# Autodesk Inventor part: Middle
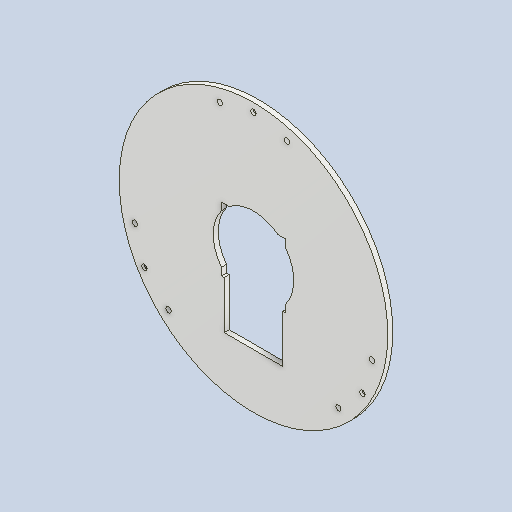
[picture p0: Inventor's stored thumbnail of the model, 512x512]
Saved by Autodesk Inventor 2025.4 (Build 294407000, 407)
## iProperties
Created: 2026-09
Part Number: Middle
Material: Generic
Document SubType Name: Modeling
Designer: AdminForWorker
Density: 1 g/cm^3
Appearance: Default
Title: mediomod v1
Author: AdminForWorker
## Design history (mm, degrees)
feature "Body1"
body "Solid1"
